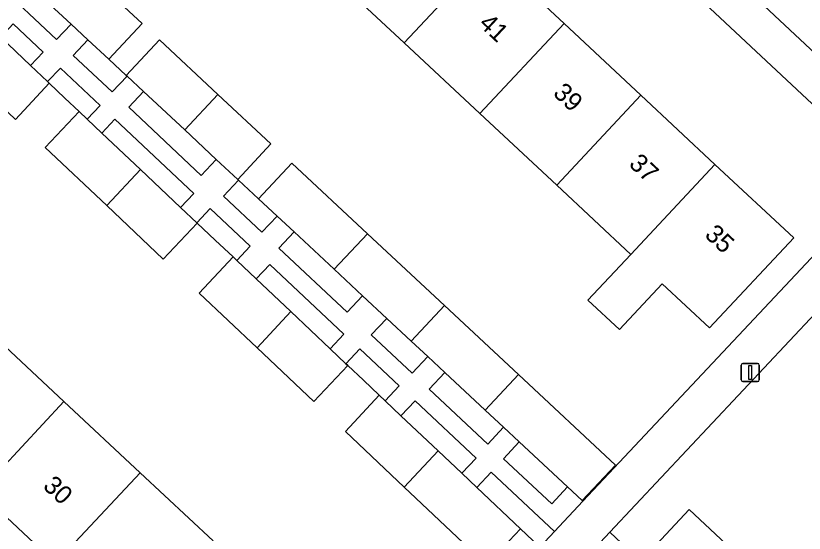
# Model space of a CAD drawing. Extents: x 159039 to 160102, y 381214 to 382524.
# Drawn here: x 159293.47 to 159336.54, y 381621.89 to 381650.18 of the extents above; entities that cross this region are included whole.
import ezdxf

# ---------------------------------------------------------------- set-up
doc = ezdxf.new("R2010")
doc.units = 0
for name, color, linetype in [('IMGEO_Erf', 7, 'Continuous'), ('IMGEO_Groenvoorziening', 7, 'Continuous'), ('IMGEO_Lichtmast', 7, 'Continuous'), ('IMGEO_Pand', 7, 'Continuous'), ('IMGEO_Pand_nummerreeks', 7, 'Continuous'), ('IMGEO_Parkeervlak_open', 7, 'Continuous'), ('IMGEO_Voetpad_open', 7, 'Continuous')]:
    doc.layers.add(name, color=color, linetype=linetype)

msp = doc.modelspace()

# ---------------------------------------------------------------- linework, layer by layer
at = {"layer": 'IMGEO_Erf'}
for points in [[(159296, 381653.818), (159300.363, 381649.749), (159298.548, 381647.807), (159299.504, 381646.915), (159301.319, 381648.857), (159304.512, 381645.879), (159307.409, 381643.176), (159305.594, 381641.234), (159305.631, 381641.199), (159306.729, 381640.175), (159308.544, 381642.117), (159312.675, 381638.264), (159316.882, 381634.34), (159320.927, 381630.567), (159326.228, 381625.621), (159324.415, 381623.677), (159324.452, 381623.642), (159341.159, 381641.45), (159309.873, 381670.73)], [(159319.291, 381653.619), (159323.418, 381649.763), (159327.622, 381645.834), (159331.664, 381642.058), (159335.965, 381638.038), (159331.365, 381633.116), (159328.779, 381635.533), (159326.442, 381633.033), (159324.728, 381634.635), (159327.064, 381637.135), (159323.023, 381640.912), (159318.819, 381644.84), (159314.692, 381648.697), (159310.663, 381652.462)], [(159322.063, 381621.17), (159321.039, 381622.138), (159319.181, 381620.174), (159314.694, 381624.42), (159311.478, 381627.462), (159313.323, 381629.437), (159312.455, 381630.259), (159311.599, 381631.069), (159309.753, 381629.093), (159306.645, 381632.034), (159303.49, 381635.019), (159305.336, 381636.994), (159304.353, 381637.923), (159303.372, 381638.851), (159301.526, 381636.876), (159298.433, 381639.802), (159295.065, 381642.988), (159296.923, 381644.952), (159296.153, 381645.681), (159295.298, 381646.49), (159293.452, 381644.514)], [(159342.745, 381639.886), (159325.918, 381621.948), (159329.688, 381618.408)], [(159295.642, 381620.259), (159291.48, 381624.148), (159287.383, 381627.978), (159283.233, 381631.855), (159279.244, 381635.583), (159278.181, 381636.588), (159272.091, 381630.15), (159281.593, 381623.601), (159298.712, 381610.727)], [(159292.003, 381632.922), (159296.1, 381629.092), (159300.262, 381625.203), (159304.249, 381621.478)], [(159328.467, 381621.276), (159330.251, 381623.188), (159333.423, 381620.217)]]:
    msp.add_lwpolyline(points, dxfattribs=at)
at = {"layer": 'IMGEO_Groenvoorziening'}
for points in [[(159301.759, 381659.594), (159300.531, 381660.74), (159292.369, 381651.992), (159295.691, 381648.875), (159296.49, 381649.727), (159294.187, 381651.875), (159296, 381653.818)], [(159293.33, 381649.731), (159292.641, 381649.003), (159294.273, 381647.46), (159294.968, 381648.194)], [(159298.548, 381647.807), (159297.408, 381648.87), (159296.607, 381648.016), (159298.739, 381646.016), (159299.546, 381646.876), (159299.504, 381646.915)], [(159295.903, 381647.317), (159295.205, 381646.578), (159295.298, 381646.49), (159296.153, 381645.681), (159296.923, 381644.952), (159297.367, 381644.532), (159298.074, 381645.28)], [(159302.697, 381643.937), (159300.444, 381646.038), (159299.635, 381645.176), (159303.598, 381641.457), (159304.418, 381642.331)], [(159298.882, 381644.522), (159298.171, 381643.771), (159300.278, 381641.778), (159302.472, 381639.703), (159303.199, 381640.472)], [(159306.729, 381640.175), (159305.631, 381641.199), (159304.808, 381640.322), (159306.914, 381638.346), (159307.743, 381639.23)], [(159304.085, 381639.641), (159303.354, 381638.868), (159303.372, 381638.851), (159304.353, 381637.923), (159305.336, 381636.994), (159305.535, 381636.805), (159306.275, 381637.586)], [(159310.861, 381636.321), (159308.673, 381638.362), (159307.842, 381637.475), (159311.573, 381633.975), (159312.414, 381634.872)], [(159307.342, 381636.585), (159306.599, 381635.799), (159308.491, 381634.009), (159310.637, 381631.98), (159311.396, 381632.782)], [(159315.067, 381632.397), (159313.735, 381633.639), (159312.89, 381632.739), (159315.126, 381630.641), (159315.978, 381631.548)], [(159312.265, 381631.966), (159311.503, 381631.16), (159311.599, 381631.069), (159312.455, 381630.259), (159313.323, 381629.437), (159313.65, 381629.128), (159314.421, 381629.943)], [(159316.911, 381630.678), (159316.057, 381629.768), (159319.251, 381626.771), (159320.114, 381627.69), (159319.112, 381628.625)], [(159315.28, 381629.138), (159314.505, 381628.319), (159316.539, 381626.395), (159317.83, 381625.174), (159318.617, 381626.006)], [(159320.97, 381626.891), (159320.106, 381625.969), (159322.744, 381623.494), (159323.613, 381624.425)], [(159319.443, 381625.232), (159318.652, 381624.396), (159321.039, 381622.138), (159322.063, 381621.17), (159322.1, 381621.135), (159322.9, 381621.988)]]:
    msp.add_lwpolyline(points, close=True, dxfattribs=at)
at = {"layer": 'IMGEO_Lichtmast'}
for p, q in [((159333.095, 381630.281), (159333.095, 381631.081)), ((159333.095, 381631.081), (159333.095, 381630.281)), ((159333.195, 381631.181), (159333.985, 381631.181)), ((159333.985, 381631.181), (159333.195, 381631.181)), ((159334.085, 381631.081), (159334.085, 381630.281)), ((159334.085, 381630.281), (159334.085, 381631.081)), ((159333.985, 381630.181), (159333.195, 381630.181)), ((159333.195, 381630.181), (159333.985, 381630.181))]:
    msp.add_line(p, q, dxfattribs=at)
msp.add_lwpolyline([(159333.515, 381631.056), (159333.665, 381631.056), (159333.665, 381630.306), (159333.515, 381630.306), (159333.515, 381631.056)], dxfattribs=at)
for centre, start, end in [((159333.195, 381631.081), 90, 180), ((159333.195, 381631.081), 90, 180), ((159333.985, 381631.081), 0, 90), ((159333.985, 381631.081), 360, 90), ((159333.195, 381630.281), 180, 270), ((159333.195, 381630.281), 180, 270), ((159333.985, 381630.281), 270, 0), ((159333.985, 381630.281), 270, 0)]:
    msp.add_arc(centre, 0.1, start, end, dxfattribs=at)
at = {"layer": 'IMGEO_Pand'}
for points in [[(159319.291, 381653.619), (159315.262, 381657.384), (159310.663, 381652.462), (159314.692, 381648.697)], [(159296, 381653.818), (159294.187, 381651.875), (159296.49, 381649.727), (159297.408, 381648.87), (159298.548, 381647.807), (159300.363, 381649.749)], [(159318.819, 381644.84), (159323.418, 381649.763), (159319.291, 381653.619), (159314.692, 381648.697)], [(159318.819, 381644.84), (159323.023, 381640.912), (159327.622, 381645.834), (159323.418, 381649.763)], [(159294.273, 381647.46), (159292.641, 381649.003), (159292.1, 381649.515), (159290.242, 381647.551), (159293.452, 381644.514), (159295.298, 381646.49), (159295.205, 381646.578)], [(159301.319, 381648.857), (159299.504, 381646.915), (159299.546, 381646.876), (159300.444, 381646.038), (159302.697, 381643.937), (159304.512, 381645.879)], [(159307.409, 381643.176), (159304.512, 381645.879), (159302.697, 381643.937), (159304.418, 381642.331), (159305.594, 381641.234)], [(159331.664, 381642.058), (159327.622, 381645.834), (159323.023, 381640.912), (159327.064, 381637.135)], [(159298.171, 381643.771), (159297.367, 381644.532), (159296.923, 381644.952), (159295.065, 381642.988), (159298.433, 381639.802), (159300.278, 381641.778)], [(159308.544, 381642.117), (159306.729, 381640.175), (159307.743, 381639.23), (159308.673, 381638.362), (159310.861, 381636.321), (159312.675, 381638.264)], [(159331.664, 381642.058), (159327.064, 381637.135), (159324.728, 381634.635), (159326.442, 381633.033), (159328.779, 381635.533), (159331.365, 381633.116), (159335.965, 381638.038)], [(159302.472, 381639.703), (159300.278, 381641.778), (159298.433, 381639.802), (159301.526, 381636.876), (159303.372, 381638.851), (159303.354, 381638.868)], [(159312.675, 381638.264), (159310.861, 381636.321), (159312.414, 381634.872), (159313.735, 381633.639), (159315.067, 381632.397), (159316.882, 381634.34)], [(159306.599, 381635.799), (159305.535, 381636.805), (159305.336, 381636.994), (159303.49, 381635.019), (159306.645, 381632.034), (159308.491, 381634.009)], [(159316.882, 381634.34), (159315.067, 381632.397), (159315.978, 381631.548), (159316.911, 381630.678), (159319.112, 381628.625), (159320.927, 381630.567)], [(159310.637, 381631.98), (159308.491, 381634.009), (159306.645, 381632.034), (159309.753, 381629.093), (159311.599, 381631.069), (159311.503, 381631.16)], [(159292.003, 381632.922), (159287.383, 381627.978), (159291.48, 381624.148), (159296.1, 381629.092)], [(159320.927, 381630.567), (159319.112, 381628.625), (159320.114, 381627.69), (159320.97, 381626.891), (159323.613, 381624.425), (159324.415, 381623.677), (159326.228, 381625.621)], [(159295.642, 381620.259), (159300.262, 381625.203), (159296.1, 381629.092), (159291.48, 381624.148)], [(159314.505, 381628.319), (159313.65, 381629.128), (159313.323, 381629.437), (159311.478, 381627.462), (159314.694, 381624.42), (159316.539, 381626.395)], [(159318.652, 381624.396), (159317.83, 381625.174), (159316.539, 381626.395), (159314.694, 381624.42), (159319.181, 381620.174), (159321.039, 381622.138)], [(159304.249, 381621.478), (159300.262, 381625.203), (159295.642, 381620.259), (159299.629, 381616.534)], [(159333.423, 381620.217), (159330.251, 381623.188), (159328.467, 381621.276), (159330.548, 381619.327), (159331.234, 381618.684), (159331.635, 381618.308)]]:
    msp.add_lwpolyline(points, close=True, dxfattribs=at)
at = {"layer": 'IMGEO_Parkeervlak_open'}
msp.add_lwpolyline([(159314.075, 381669.48), (159320.61, 381663.612), (159331.275, 381653.611), (159341.081, 381644.432)], dxfattribs=at)
at = {"layer": 'IMGEO_Voetpad_open'}
for points in [[(159302.886, 381680.595), (159301.466, 381678.598), (159308.878, 381671.662), (159309.873, 381670.73), (159341.159, 381641.45), (159342.745, 381639.886), (159393.542, 381592.228), (159394.004, 381591.525), (159396.752, 381594.079), (159396.201, 381594.694), (159396.104, 381594.741)], [(159341.081, 381644.432), (159331.275, 381653.611), (159320.61, 381663.612), (159314.075, 381669.48)], [(159293.33, 381649.731), (159294.968, 381648.194), (159294.273, 381647.46), (159295.205, 381646.578), (159295.903, 381647.317), (159298.074, 381645.28), (159297.367, 381644.532), (159298.171, 381643.771), (159298.882, 381644.522), (159303.199, 381640.472), (159302.472, 381639.703), (159303.354, 381638.868), (159304.085, 381639.641), (159306.275, 381637.586), (159305.535, 381636.805), (159306.599, 381635.799), (159307.342, 381636.585), (159311.396, 381632.782), (159310.637, 381631.98), (159311.503, 381631.16), (159312.265, 381631.966), (159314.421, 381629.943), (159313.65, 381629.128), (159314.505, 381628.319), (159315.28, 381629.138), (159318.617, 381626.006), (159317.83, 381625.174), (159318.652, 381624.396), (159319.443, 381625.232), (159322.9, 381621.988), (159324.452, 381623.642), (159324.415, 381623.677), (159323.613, 381624.425), (159322.744, 381623.494), (159320.106, 381625.969), (159320.97, 381626.891), (159320.114, 381627.69), (159319.251, 381626.771), (159316.057, 381629.768), (159316.911, 381630.678), (159315.978, 381631.548), (159315.126, 381630.641), (159312.89, 381632.739), (159313.735, 381633.639), (159312.414, 381634.872), (159311.573, 381633.975), (159307.842, 381637.475), (159308.673, 381638.362), (159307.743, 381639.23), (159306.914, 381638.346), (159304.808, 381640.322), (159305.631, 381641.199), (159305.594, 381641.234), (159304.418, 381642.331), (159303.598, 381641.457), (159299.635, 381645.176), (159300.444, 381646.038), (159299.546, 381646.876), (159298.739, 381646.016), (159296.607, 381648.016), (159297.408, 381648.87), (159296.49, 381649.727), (159295.691, 381648.875), (159292.369, 381651.992)], [(159329.688, 381618.408), (159325.918, 381621.948), (159324.597, 381620.539)]]:
    msp.add_lwpolyline(points, dxfattribs=at)
msp.add_lwpolyline([(159342.745, 381639.886), (159341.159, 381641.45), (159324.452, 381623.642), (159322.9, 381621.988), (159322.1, 381621.135), (159306.532, 381604.542), (159308.288, 381603.153), (159324.597, 381620.539), (159325.918, 381621.948)], close=True, dxfattribs=at)

# ---------------------------------------------------------------- texts
at = {"layer": 'IMGEO_Pand_nummerreeks'}
for s, rotation, p in [('41', 316.9393, (159318.709, 381649.676)), ('39', 316.9393, (159322.768, 381645.882)), ('37', 316.9393, (159326.909, 381642.012)), ('35', 316.9393, (159331.051, 381638.141)), ('30', 316.9392, (159294.898, 381624.404))]:
    msp.add_text(s, height=1, rotation=rotation, dxfattribs=at).set_placement(p)

doc.saveas('drawing.dxf')
